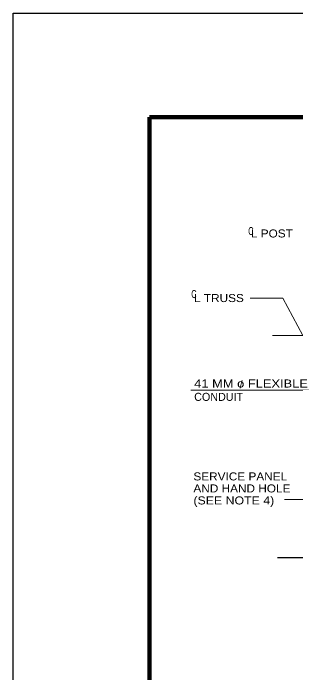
# Model space of a CAD drawing. Extents: x 312601.858 to 312602.699, y 144420.109 to 144420.704.
# Drawn here: x 312601.8578 to 312601.9635, y 144420.4564 to 144420.7035 of the extents above; entities that cross this region are included whole.
import ezdxf
from ezdxf.enums import TextEntityAlignment as Align

# ---------------------------------------------------------------- set-up
doc = ezdxf.new("R2010")
doc.units = 0
doc.header["$LTSCALE"] = 0.0012
for name, color, linetype, lineweight in [('1', 7, 'Continuous', 25), ('2', 7, 'Continuous', 25), ('39', 7, 'Continuous', 13)]:
    doc.layers.add(name, color=color, linetype=linetype, lineweight=lineweight)

msp = doc.modelspace()

# ---------------------------------------------------------------- linework, layer by layer
at = {"layer": '1', "lineweight": 13}
for p, q in [((312601.9548, 144420.5828), (312601.973, 144420.5828)), ((312601.9243, 144420.5623), (312601.9878, 144420.5623)), ((312601.981, 144420.5213), (312601.9593, 144420.5213)), ((312601.981, 144420.5213), (312601.9605, 144420.5213))]:
    msp.add_line(p, q, dxfattribs=at)
at = {"layer": '1'}
msp.add_line((312601.9566, 144420.4996), (312602.0096, 144420.4996), dxfattribs=at)
at = {"layer": '2', "lineweight": 13}
for p, q in [((312601.9464, 144420.5967), (312601.9586, 144420.5967)), ((312601.9586, 144420.5967), (312601.9661, 144420.5828))]:
    msp.add_line(p, q, dxfattribs=at)
at = {"layer": '39', "lineweight": 25}
for p, q in [((312601.8578, 144420.1095), (312601.8578, 144420.7035)), ((312601.8578, 144420.7035), (312602.6988, 144420.7035))]:
    msp.add_line(p, q, dxfattribs=at)
at = {"layer": '39', "lineweight": 158}
for p, q in [((312601.9088, 144420.1247), (312601.9088, 144420.6645)), ((312601.9088, 144420.6645), (312602.6838, 144420.6645))]:
    msp.add_line(p, q, dxfattribs=at)

# ---------------------------------------------------------------- texts
at = {"layer": '1'}
for s, width, p in [('41 MM o FLEXIBLE', 1.2, (312601.9255, 144420.5633)), ('SERVICE PANEL', 1.1, (312601.9252, 144420.5285)), ('AND HAND HOLE', 1.1, (312601.9252, 144420.524)), ('(SEE NOTE 4)', 1.15, (312601.9252, 144420.5195))]:
    msp.add_text(s, height=0.003, dxfattribs=dict(at, width=width)).set_placement(p)
msp.add_text('CONDUIT', height=0.003, dxfattribs=at).set_placement((312601.9255, 144420.5583))
at = {"layer": '2'}
for s, width, p in [('C', 0.6, (312601.9467, 144420.6204)), ('L POST', 1.1, (312601.95455, 144420.6195)), ('C', 0.6, (312601.9254, 144420.5968)), ('L TRUSS', 1.1, (312601.93475, 144420.5953))]:
    msp.add_text(s, height=0.003, dxfattribs=dict(at, width=width)).set_placement(p, align=Align.CENTER)
msp.add_text('/', height=0.003, dxfattribs=at).set_placement((312601.94305, 144420.563), align=Align.CENTER)

doc.saveas('drawing.dxf')
